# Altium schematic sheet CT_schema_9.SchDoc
size 287 x 160 mm
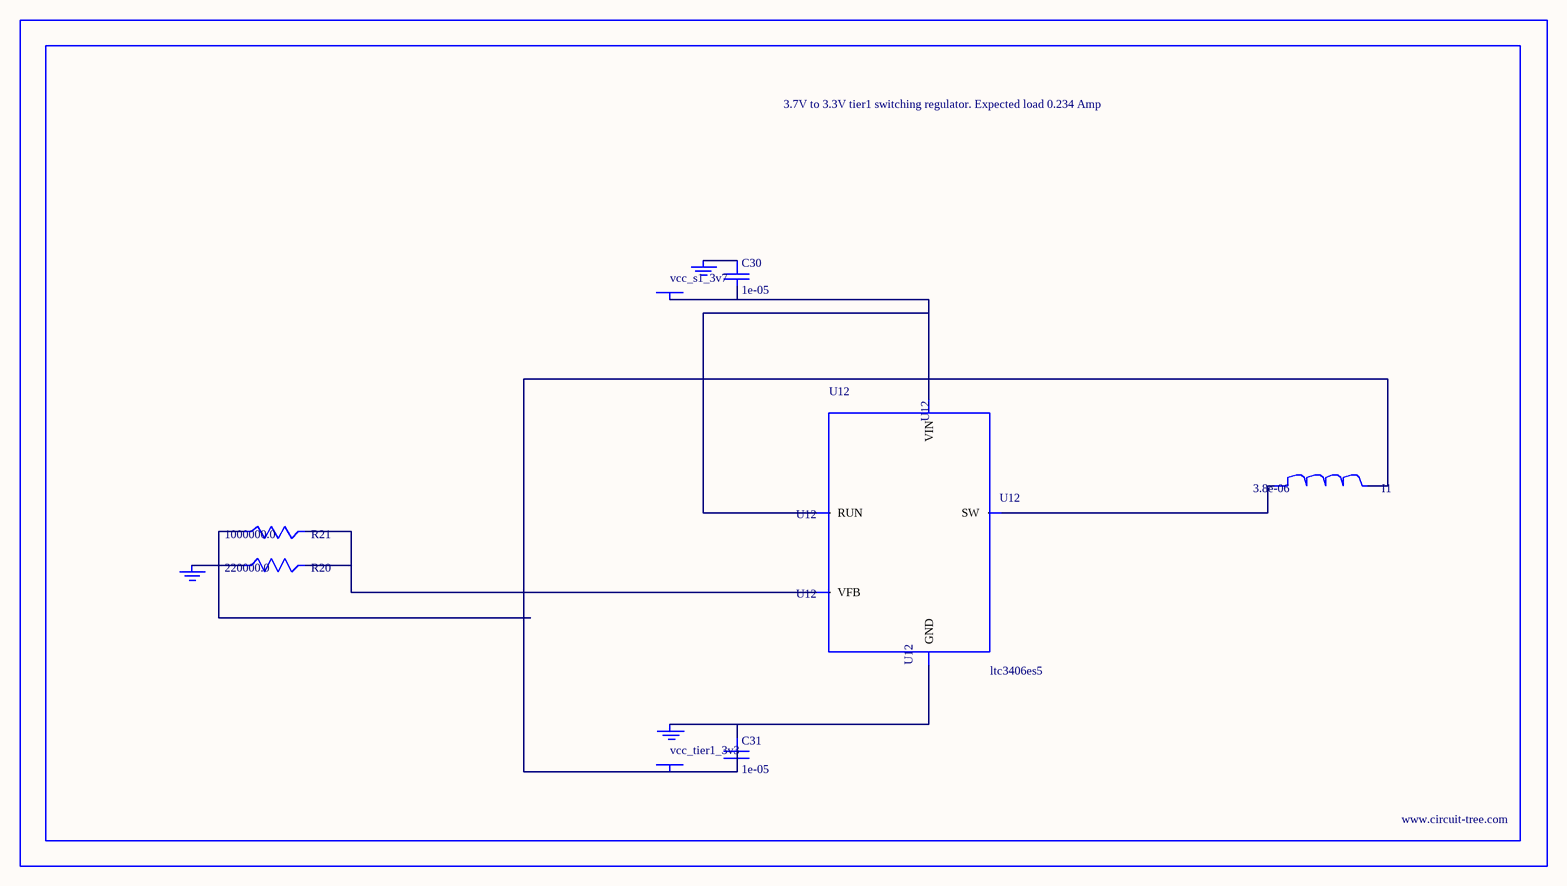
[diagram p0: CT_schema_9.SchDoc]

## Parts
BORDER8  (no value)
C30  1e-05  [C0805]
C31  1e-05  [C0805]
GND_INSTANCE_8_0  (no value)
GND_INSTANCE_8_1  (no value)
GND_INSTANCE_8_2  (no value)
I1  3.8e-06  [DR1040]
POWER_INSTANCE_8_0  vcc_tier1_3v3
POWER_INSTANCE_8_1  vcc_s1_3v7
R20  220000.0  [R0603]
R21  1000000.0  [R0603]
U12  ltc3406es5  [TSOT-23-5]

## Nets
NetC30_1: C30.1 GND_INSTANCE_8_1.0(GND)
NetC30_2: C30.2 POWER_INSTANCE_8_1.0(PWR) U12.1(RUN) U12.4(VIN)
NetC31_1: C31.1 GND_INSTANCE_8_0.0(GND) U12.2(GND)
NetC31_2: C31.2 I1.2 POWER_INSTANCE_8_0.0(PWR) R21.1
NetGND_INSTANCE_8_2_0: GND_INSTANCE_8_2.0(GND) R20.1
NetI1_1: I1.1 U12.3(SW)
NetR20_2: R20.2 R21.2 U12.5(VFB)

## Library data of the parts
BORDER8 = BORDER_PAGE8
C30 C31 = C0805C106K8RACTU
GND_INSTANCE_8_0-GND_INSTANCE_8_2 = GND
I1 = DR1040-3R8-R
POWER_INSTANCE_8_0 POWER_INSTANCE_8_1 = PWR
R20 = RC0603JR-07220KL
R21 = RC0603JR-071ML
